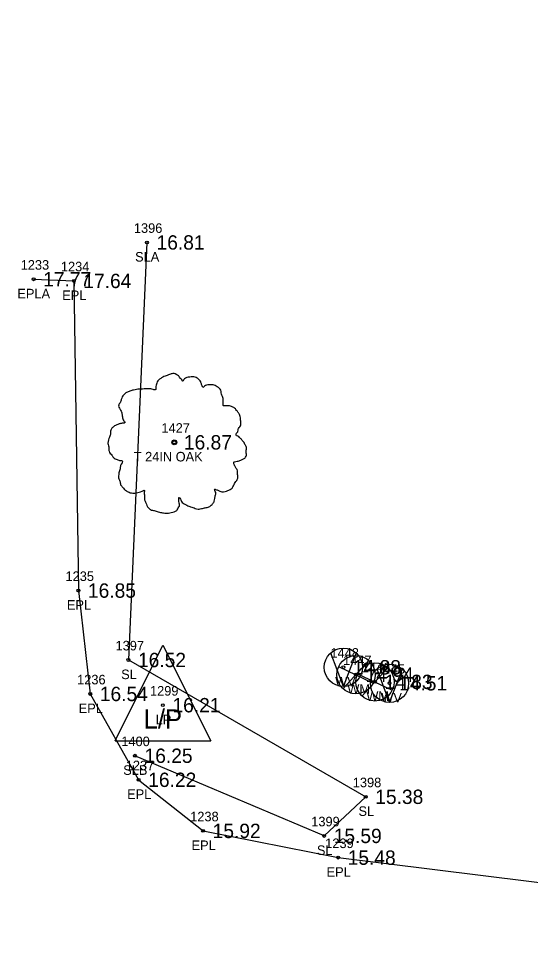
# Model space of a CAD drawing. Extents: x 2072307 to 2072993, y 127574 to 129736.
# Drawn here: x 2072733.1 to 2072786.6, y 128606.7 to 128703 of the extents above; entities that cross this region are included whole.
import ezdxf

# ---------------------------------------------------------------- set-up
doc = ezdxf.new("R2010")
doc.units = 0
for name, color, linetype in [('RD_EX_Road', 7, 'Continuous'), ('RD_EX_Road_txCode', 7, 'Continuous'), ('RD_EX_TX_Road_ELEV', 7, 'Continuous'), ('RD_EX_TX_UT_ELEV', 7, 'Continuous'), ('RD_EX_TX_VEG_ELEV', 7, 'Continuous'), ('RD_EX_UT', 7, 'Continuous'), ('RD_EX_UT_txCode', 7, 'Continuous'), ('RD_EX_VEG', 7, 'Continuous'), ('RD_EX_VEG_txCode', 7, 'Continuous'), ('RD_SMD_Locator', 7, 'Continuous')]:
    doc.layers.add(name, color=color, linetype=linetype)

msp = doc.modelspace()

# ---------------------------------------------------------------- linework, layer by layer
at = {"layer": 'RD_EX_Road'}
msp.add_lwpolyline([(2072734.641, 128675.725), (2072738.843, 128675.552), (2072739.325, 128643.176), (2072740.565, 128632.368), (2072745.624, 128623.392), (2072752.359, 128618.05), (2072766.472, 128615.254), (2072791.472, 128612.165), (2072820.403, 128606.687), (2072833.346, 128608.3), (2072843.024, 128612.288), (2072850.798, 128617.182), (2072857.929, 128632.794), (2072859.401, 128640.059), (2072859.22, 128649.543), (2072857.789, 128659.623), (2072853.074, 128669.777), (2072812.002, 128702.996)], dxfattribs=at)
at = {"layer": 'RD_EX_UT'}
for p, q in [((2072743.157, 128627.469), (2072748.157, 128637.469)), ((2072748.157, 128637.469), (2072753.157, 128627.469)), ((2072767.02, 128633.163), (2072765.717, 128636.646)), ((2072767.02, 128633.163), (2072768.343, 128636.608)), ((2072766.507, 128635.221), (2072770.137, 128633.508)), ((2072766.988, 128632.925), (2072769.655, 128635.822)), ((2072768.972, 128632.173), (2072771.639, 128635.07)), ((2072768.49, 128634.469), (2072772.121, 128632.756)), ((2072771.846, 128631.487), (2072770.542, 128634.97)), ((2072771.846, 128631.487), (2072773.168, 128634.932)), ((2072743.157, 128627.469), (2072753.157, 128627.469))]:
    msp.add_line(p, q, dxfattribs=at)
for centre in [(2072767.02, 128635.156), (2072768.34, 128634.384), (2072770.324, 128633.631), (2072771.846, 128633.48)]:
    msp.add_circle(centre, 2, dxfattribs=at)
at = {"layer": 'RD_EX_VEG'}
msp.add_lwpolyline([(2072746.495, 128679.575), (2072744.555, 128635.919), (2072769.356, 128621.615), (2072765.012, 128617.527), (2072745.24, 128625.909)], dxfattribs=at)
for centre, radius in [((2072749.353, 128658.676), 0.25), ((2072749.341, 128658.657), 0.0001)]:
    msp.add_circle(centre, radius, dxfattribs=at)
for points in [[(2072749.485, 128665.843), (2072749.185, 128665.868), (2072748.861, 128665.768), (2072748.611, 128665.668), (2072748.386, 128665.593), (2072748.161, 128665.493), (2072747.861, 128665.318), (2072747.636, 128665.118), (2072747.511, 128664.868), (2072747.461, 128664.644), (2072747.411, 128664.369), (2072747.411, 128664.194), (2072747.286, 128664.169), (2072747.136, 128664.194), (2072746.886, 128664.269), (2072746.637, 128664.269), (2072746.387, 128664.269), (2072746.037, 128664.244), (2072745.687, 128664.244), (2072745.412, 128664.194), (2072745.087, 128664.144), (2072744.712, 128664.019), (2072744.363, 128663.894), (2072744.063, 128663.644), (2072743.813, 128663.169), (2072743.688, 128662.819), (2072743.538, 128662.569), (2072743.688, 128662.12), (2072743.863, 128661.77), (2072743.888, 128661.57), (2072743.963, 128661.145), (2072744.063, 128660.92), (2072744.188, 128660.72), (2072744.113, 128660.695), (2072743.738, 128660.645), (2072743.438, 128660.545), (2072743.013, 128660.32), (2072742.788, 128660.096), (2072742.688, 128659.771), (2072742.663, 128659.421), (2072742.563, 128659.221), (2072742.488, 128658.946), (2072742.463, 128658.871), (2072742.413, 128658.546), (2072742.513, 128658.096), (2072742.538, 128657.747), (2072742.663, 128657.522), (2072742.813, 128657.347), (2072742.988, 128657.097), (2072743.388, 128656.872), (2072743.713, 128656.772), (2072743.913, 128656.747), (2072743.738, 128656.247), (2072743.688, 128655.897), (2072743.563, 128655.498), (2072743.563, 128655.423), (2072743.513, 128654.948), (2072743.663, 128654.623), (2072743.738, 128654.248), (2072743.913, 128654.023), (2072744.188, 128653.723), (2072744.512, 128653.498), (2072745.012, 128653.373), (2072745.412, 128653.398), (2072745.987, 128653.573), (2072746.237, 128653.648), (2072746.212, 128653.473), (2072746.237, 128653.099), (2072746.237, 128652.674), (2072746.387, 128652.349), (2072746.487, 128652.074), (2072746.637, 128651.824), (2072746.961, 128651.599), (2072747.361, 128651.524), (2072747.786, 128651.374), (2072748.236, 128651.299), (2072748.736, 128651.274), (2072749.335, 128651.424), (2072749.61, 128651.549), (2072749.71, 128651.724), (2072749.91, 128652.099), (2072749.86, 128652.324), (2072749.885, 128652.924), (2072749.985, 128652.749), (2072750.16, 128652.399), (2072750.66, 128652.099), (2072751.06, 128651.924), (2072751.534, 128651.774), (2072751.834, 128651.699), (2072752.309, 128651.774), (2072752.684, 128651.849), (2072753.059, 128651.974), (2072753.359, 128652.249), (2072753.534, 128652.524), (2072753.584, 128652.799), (2072753.658, 128653.174), (2072753.708, 128653.348)], [(2072753.708, 128653.348), (2072753.634, 128653.523), (2072753.584, 128653.773), (2072753.658, 128653.748), (2072753.833, 128653.698), (2072754.108, 128653.573), (2072754.333, 128653.498), (2072754.658, 128653.523), (2072754.933, 128653.623), (2072755.383, 128653.898), (2072755.658, 128654.373), (2072755.932, 128654.773), (2072756.007, 128655.098), (2072755.957, 128655.323), (2072755.932, 128655.822), (2072755.733, 128656.072), (2072755.683, 128656.197), (2072755.583, 128656.597), (2072755.658, 128656.647), (2072755.932, 128656.697), (2072756.307, 128656.822), (2072756.582, 128656.947), (2072756.807, 128657.122), (2072756.882, 128657.347), (2072756.857, 128657.747), (2072756.907, 128658.146), (2072756.832, 128658.296), (2072756.732, 128658.446), (2072756.657, 128658.646), (2072756.507, 128658.796), (2072756.407, 128658.946), (2072756.307, 128659.046), (2072756.182, 128659.196), (2072756.007, 128659.321), (2072755.858, 128659.371), (2072755.808, 128659.521), (2072755.957, 128659.721), (2072756.007, 128659.821), (2072756.032, 128660.046), (2072756.257, 128660.395), (2072756.307, 128660.795), (2072756.257, 128661.22), (2072756.207, 128661.495), (2072756.057, 128661.77), (2072755.858, 128662.02), (2072755.733, 128662.195), (2072755.558, 128662.32), (2072755.233, 128662.445), (2072754.983, 128662.494), (2072754.633, 128662.494), (2072754.433, 128662.544), (2072754.458, 128662.594), (2072754.458, 128662.744), (2072754.458, 128663.019), (2072754.383, 128663.469), (2072754.233, 128663.969), (2072754.233, 128663.994), (2072754.133, 128664.244), (2072753.908, 128664.444), (2072753.733, 128664.544), (2072753.534, 128664.669), (2072753.284, 128664.694), (2072752.984, 128664.694), (2072752.709, 128664.644), (2072752.509, 128664.544), (2072752.334, 128664.419), (2072752.259, 128664.569), (2072752.159, 128664.868), (2072752.109, 128665.018), (2072751.959, 128665.193), (2072751.734, 128665.393), (2072751.284, 128665.518), (2072750.66, 128665.443), (2072750.36, 128665.243), (2072750.21, 128665.068), (2072750.16, 128665.193), (2072749.96, 128665.393), (2072749.86, 128665.568), (2072749.685, 128665.693), (2072749.535, 128665.793), (2072749.435, 128665.843)]]:
    msp.add_spline(points, degree=3, dxfattribs=at)
at = {"layer": 'RD_SMD_Locator'}
for centre in [(2072746.495, 128679.575), (2072734.641, 128675.725), (2072738.843, 128675.552), (2072749.353, 128658.676), (2072739.325, 128643.176), (2072744.555, 128635.919), (2072767.02, 128635.156), (2072768.34, 128634.384), (2072770.324, 128633.631), (2072771.846, 128633.48), (2072740.565, 128632.368), (2072748.157, 128631.193), (2072745.24, 128625.909), (2072745.624, 128623.392), (2072769.356, 128621.615), (2072752.359, 128618.05), (2072765.012, 128617.527), (2072766.472, 128615.254)]:
    msp.add_circle(centre, 0.15, dxfattribs=at)

# ---------------------------------------------------------------- texts
at = {"layer": 'RD_EX_Road_txCode'}
for s, p in [('1233', (2072733.295, 128676.725)), ('1234', (2072737.497, 128676.552)), ('EPLA', (2072732.948, 128673.725)), ('EPL', (2072737.638, 128673.552)), ('1235', (2072737.979, 128644.176)), ('EPL', (2072738.121, 128641.176)), ('1236', (2072739.195, 128633.368)), ('EPL', (2072739.36, 128630.368)), ('1237', (2072744.278, 128624.392)), ('EPL', (2072744.419, 128621.392)), ('1238', (2072751.013, 128619.05)), ('EPL', (2072751.155, 128616.05)), ('1239', (2072765.125, 128616.254)), ('EPL', (2072765.267, 128613.254))]:
    msp.add_text(s, height=1, dxfattribs=at).set_placement(p)
at = {"layer": 'RD_EX_TX_Road_ELEV'}
for s, p in [('17.77', (2072735.641, 128674.975)), ('17.64', (2072739.843, 128674.802)), ('16.85', (2072740.325, 128642.426)), ('16.54', (2072741.565, 128631.618)), ('16.22', (2072746.624, 128622.642)), ('15.92', (2072753.359, 128617.3)), ('15.48', (2072767.472, 128614.504))]:
    msp.add_text(s, height=1.5, dxfattribs=at).set_placement(p)
at = {"layer": 'RD_EX_TX_UT_ELEV'}
for s, p in [('14.88', (2072768.02, 128634.406)), ('14.94', (2072769.34, 128633.634)), ('14.83', (2072771.324, 128632.881)), ('14.51', (2072772.846, 128632.73)), ('16.21', (2072749.157, 128630.443))]:
    msp.add_text(s, height=1.5, dxfattribs=at).set_placement(p)
at = {"layer": 'RD_EX_TX_VEG_ELEV'}
for s, p in [('16.81', (2072747.495, 128678.825)), ('16.87', (2072750.353, 128657.926)), ('16.52', (2072745.555, 128635.169)), ('16.25', (2072746.24, 128625.159)), ('15.38', (2072770.356, 128620.865)), ('15.59', (2072766.012, 128616.777))]:
    msp.add_text(s, height=1.5, dxfattribs=at).set_placement(p)
at = {"layer": 'RD_EX_UT'}
msp.add_text('L/P', height=2, dxfattribs=at).set_placement((2072746.148, 128628.751))
at = {"layer": 'RD_EX_UT_txCode'}
for s, p in [('1448', (2072765.674, 128636.156)), ('1447', (2072766.994, 128635.384)), ('1446', (2072768.954, 128634.631)), ('1445', (2072770.5, 128634.48)), ('WV', (2072766.162, 128633.156)), ('1299', (2072746.81, 128632.193)), ('WM', (2072767.435, 128632.384)), ('WM', (2072769.418, 128631.631)), ('WV', (2072770.988, 128631.48)), ('LP', (2072747.401, 128629.193))]:
    msp.add_text(s, height=1, dxfattribs=at).set_placement(p)
at = {"layer": 'RD_EX_VEG_txCode'}
for s, p in [('1396', (2072745.125, 128680.575)), ('SLA', (2072745.251, 128677.575)), ('1427', (2072748.007, 128659.676)), ('T 24IN OAK', (2072745.109, 128656.676)), ('1397', (2072743.209, 128636.919)), ('SL', (2072743.799, 128633.919)), ('1400', (2072743.814, 128626.909)), ('SLB', (2072744.011, 128623.909)), ('1398', (2072768.009, 128622.615)), ('SL', (2072768.6, 128619.615)), ('1399', (2072763.665, 128618.527)), ('SL', (2072764.256, 128615.527))]:
    msp.add_text(s, height=1, dxfattribs=at).set_placement(p)

doc.saveas('drawing.dxf')
